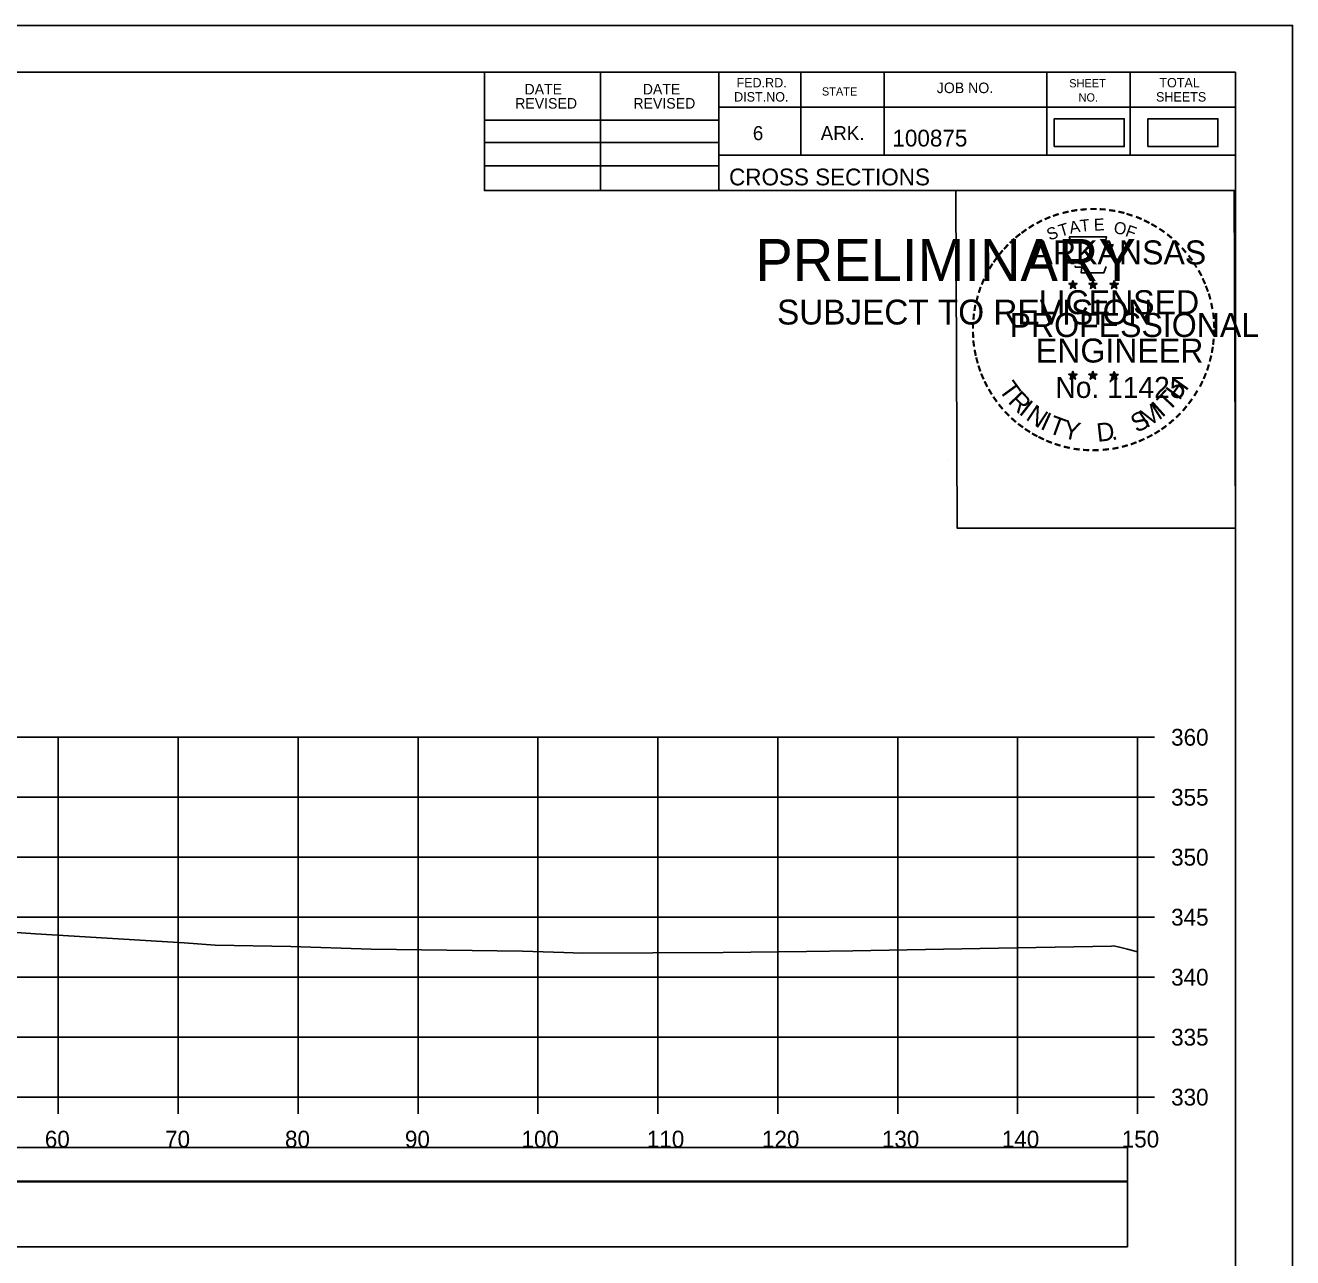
# Model space of a CAD drawing. Extents: x 1368122 to 1710785, y 373130 to 557566.
# Drawn here: x 1368746.1 to 1368851.8, y 374734.3 to 374837 of the extents above; entities that cross this region are included whole.
import ezdxf

# ---------------------------------------------------------------- set-up
doc = ezdxf.new("R2010")
doc.units = 0
for name, color, linetype in [('R_Alt Surface', 7, 'Continuous'), ('R_Axis', 7, 'Continuous'), ('R_Axis Annot', 7, 'Continuous'), ('R_Border', 7, 'Continuous'), ('R_Border PE', 7, 'Continuous'), ('R_Border Prem', 7, 'Continuous'), ('R_Drive', 7, 'Continuous'), ('R_Exist Surface', 7, 'Continuous'), ('R_Grid', 7, 'Continuous'), ('R_No Plot', 7, 'Continuous')]:
    doc.layers.add(name, color=color, linetype=linetype)

msp = doc.modelspace()

# ---------------------------------------------------------------- linework, layer by layer
at = {"layer": 'R_Alt Surface'}
for points in [[(1368539.73, 374740.67), (1368838.03, 374740.67), (1368838.03, 374743.48), (1368539.73, 374743.48)], [(1368539.73, 374735.2), (1368838.03, 374735.2), (1368838.03, 374740.61), (1368539.73, 374740.61)]]:
    msp.add_lwpolyline(points, close=True, dxfattribs=at)
at = {"layer": 'R_Axis'}
for p, q in [((1368838.88, 374747.68), (1368838.88, 374777.68)), ((1368840.28, 374777.68), (1368838.88, 374777.68)), ((1368840.28, 374772.68), (1368838.88, 374772.68)), ((1368840.28, 374767.68), (1368838.88, 374767.68)), ((1368840.28, 374762.68), (1368838.88, 374762.68)), ((1368840.28, 374757.68), (1368838.88, 374757.68)), ((1368840.28, 374752.68), (1368838.88, 374752.68)), ((1368538.88, 374747.68), (1368838.88, 374747.68)), ((1368748.88, 374746.28), (1368748.88, 374747.68)), ((1368758.88, 374746.28), (1368758.88, 374747.68)), ((1368768.88, 374746.28), (1368768.88, 374747.68)), ((1368778.88, 374746.28), (1368778.88, 374747.68)), ((1368788.88, 374746.28), (1368788.88, 374747.68)), ((1368798.88, 374746.28), (1368798.88, 374747.68)), ((1368808.88, 374746.28), (1368808.88, 374747.68)), ((1368818.88, 374746.28), (1368818.88, 374747.68)), ((1368828.88, 374746.28), (1368828.88, 374747.68)), ((1368838.88, 374746.28), (1368838.88, 374747.68)), ((1368840.28, 374747.68), (1368838.88, 374747.68))]:
    msp.add_line(p, q, dxfattribs=at)
at = {"layer": 'R_Border'}
for p, q in [((1368530.88, 374833.14), (1368847.06, 374833.14)), ((1368784.42, 374823.26), (1368784.42, 374833.14)), ((1368794.1, 374823.26), (1368794.1, 374833.14)), ((1368803.96, 374833.14), (1368803.96, 374823.26)), ((1368810.8, 374833.14), (1368810.8, 374826.2)), ((1368817.74, 374833.14), (1368817.74, 374826.2)), ((1368831.32, 374833.14), (1368831.32, 374826.2)), ((1368838.26, 374833.14), (1368838.26, 374826.2)), ((1368847.06, 374627.68), (1368847.06, 374833.14)), ((1368847.06, 374830.2), (1368803.96, 374830.2)), ((1368847.06, 374830.22), (1368847.06, 374830.22)), ((1368784.42, 374829.12), (1368803.96, 374829.12)), ((1368784.42, 374827.26), (1368803.96, 374827.26)), ((1368847.06, 374826.2), (1368803.96, 374826.2)), ((1368806.92, 374826.2), (1368847.06, 374826.2)), ((1368784.42, 374825.32), (1368803.96, 374825.32)), ((1368847.06, 374823.26), (1368784.42, 374823.26))]:
    msp.add_line(p, q, dxfattribs=at)
at = {"layer": 'R_Border PE'}
for p, q in [((1368833.49, 374815.76), (1368833.45, 374815.51)), ((1368833.49, 374815.4), (1368833.49, 374815.76)), ((1368833.49, 374815.76), (1368833.54, 374815.51)), ((1368835.16, 374815.76), (1368835.12, 374815.51)), ((1368835.16, 374815.4), (1368835.16, 374815.76)), ((1368835.16, 374815.76), (1368835.21, 374815.51)), ((1368836.93, 374815.75), (1368836.89, 374815.5)), ((1368836.93, 374815.39), (1368836.93, 374815.75)), ((1368836.93, 374815.75), (1368836.98, 374815.5)), ((1368833.15, 374815.51), (1368833.49, 374815.4)), ((1368833.15, 374815.51), (1368833.4, 374815.47)), ((1368833.15, 374815.51), (1368833.38, 374815.39)), ((1368833.28, 374815.1), (1368833.49, 374815.4)), ((1368833.28, 374815.1), (1368833.4, 374815.35)), ((1368833.28, 374815.1), (1368833.49, 374815.32)), ((1368833.84, 374815.51), (1368833.49, 374815.4)), ((1368833.71, 374815.1), (1368833.49, 374815.4)), ((1368833.71, 374815.1), (1368833.49, 374815.32)), ((1368833.84, 374815.51), (1368833.56, 374815.46)), ((1368833.71, 374815.1), (1368833.57, 374815.39)), ((1368833.84, 374815.51), (1368833.64, 374815.41)), ((1368834.82, 374815.51), (1368835.16, 374815.4)), ((1368834.82, 374815.51), (1368835.07, 374815.47)), ((1368834.82, 374815.51), (1368835.05, 374815.39)), ((1368834.95, 374815.1), (1368835.16, 374815.4)), ((1368834.95, 374815.1), (1368835.07, 374815.35)), ((1368834.95, 374815.1), (1368835.16, 374815.32)), ((1368835.51, 374815.51), (1368835.16, 374815.4)), ((1368835.38, 374815.1), (1368835.16, 374815.4)), ((1368835.38, 374815.1), (1368835.16, 374815.32)), ((1368835.51, 374815.51), (1368835.23, 374815.46)), ((1368835.38, 374815.1), (1368835.24, 374815.39)), ((1368835.51, 374815.51), (1368835.31, 374815.41)), ((1368836.58, 374815.5), (1368836.93, 374815.39)), ((1368836.58, 374815.5), (1368836.83, 374815.45)), ((1368836.58, 374815.5), (1368836.82, 374815.38)), ((1368836.71, 374815.09), (1368836.93, 374815.39)), ((1368836.71, 374815.09), (1368836.84, 374815.33)), ((1368836.71, 374815.09), (1368836.93, 374815.31)), ((1368837.28, 374815.5), (1368836.93, 374815.39)), ((1368837.14, 374815.09), (1368836.93, 374815.39)), ((1368837.14, 374815.09), (1368836.93, 374815.3)), ((1368837.28, 374815.5), (1368836.99, 374815.45)), ((1368837.14, 374815.09), (1368837, 374815.38)), ((1368837.28, 374815.5), (1368837.07, 374815.4)), ((1368833.49, 374808.19), (1368833.45, 374807.94)), ((1368833.49, 374807.83), (1368833.49, 374808.19)), ((1368833.49, 374808.19), (1368833.54, 374807.94)), ((1368835.16, 374808.19), (1368835.12, 374807.94)), ((1368835.16, 374807.83), (1368835.16, 374808.19)), ((1368835.16, 374808.19), (1368835.21, 374807.94)), ((1368836.93, 374808.18), (1368836.89, 374807.93)), ((1368836.93, 374807.82), (1368836.93, 374808.18)), ((1368836.93, 374808.18), (1368836.98, 374807.93)), ((1368833.14, 374807.94), (1368833.49, 374807.83)), ((1368833.14, 374807.94), (1368833.39, 374807.89)), ((1368833.14, 374807.94), (1368833.38, 374807.82)), ((1368833.27, 374807.53), (1368833.49, 374807.83)), ((1368833.27, 374807.53), (1368833.4, 374807.77)), ((1368833.27, 374807.53), (1368833.49, 374807.75)), ((1368833.84, 374807.94), (1368833.49, 374807.83)), ((1368833.7, 374807.53), (1368833.49, 374807.83)), ((1368833.7, 374807.53), (1368833.49, 374807.74)), ((1368833.84, 374807.94), (1368833.55, 374807.89)), ((1368833.7, 374807.53), (1368833.57, 374807.82)), ((1368833.84, 374807.94), (1368833.63, 374807.84)), ((1368834.81, 374807.94), (1368835.16, 374807.83)), ((1368834.81, 374807.94), (1368835.06, 374807.89)), ((1368834.81, 374807.94), (1368835.05, 374807.82)), ((1368834.94, 374807.53), (1368835.16, 374807.83)), ((1368834.94, 374807.53), (1368835.07, 374807.77)), ((1368834.94, 374807.53), (1368835.16, 374807.75)), ((1368835.51, 374807.94), (1368835.16, 374807.83)), ((1368835.37, 374807.53), (1368835.16, 374807.83)), ((1368835.37, 374807.53), (1368835.16, 374807.74)), ((1368835.51, 374807.94), (1368835.22, 374807.89)), ((1368835.37, 374807.53), (1368835.24, 374807.82)), ((1368835.51, 374807.94), (1368835.3, 374807.84)), ((1368836.58, 374807.93), (1368836.93, 374807.82)), ((1368836.58, 374807.93), (1368836.83, 374807.88)), ((1368836.58, 374807.93), (1368836.81, 374807.81)), ((1368836.71, 374807.52), (1368836.93, 374807.82)), ((1368836.71, 374807.52), (1368836.84, 374807.76)), ((1368836.71, 374807.52), (1368836.92, 374807.74)), ((1368837.14, 374807.52), (1368836.92, 374807.73)), ((1368837.27, 374807.93), (1368836.93, 374807.82)), ((1368837.14, 374807.52), (1368836.93, 374807.82)), ((1368837.27, 374807.93), (1368836.99, 374807.88)), ((1368837.14, 374807.52), (1368837, 374807.81)), ((1368837.27, 374807.93), (1368837.07, 374807.83))]:
    msp.add_line(p, q, dxfattribs=at)
for points in [[(1368833.19, 374819.39), (1368833.46, 374818.56)], [(1368836.7, 374818.47), (1368836.84, 374818.75), (1368836.15, 374818.73), (1368836.3, 374819.39), (1368833.19, 374819.39)], [(1368833.68, 374816.97), (1368833.68, 374816.88), (1368834.24, 374816.86), (1368834.19, 374816.39), (1368836.06, 374816.39), (1368836.26, 374816.92)], [(1368833.49, 374815.76), (1368833.71, 374815.1), (1368833.15, 374815.51), (1368833.84, 374815.51), (1368833.28, 374815.1), (1368833.49, 374815.76)], [(1368835.16, 374815.76), (1368835.38, 374815.1), (1368834.82, 374815.51), (1368835.51, 374815.51), (1368834.95, 374815.1), (1368835.16, 374815.76)], [(1368836.93, 374815.75), (1368837.14, 374815.09), (1368836.58, 374815.5), (1368837.28, 374815.5), (1368836.71, 374815.09), (1368836.93, 374815.75)], [(1368833.49, 374808.19), (1368833.7, 374807.53), (1368833.14, 374807.94), (1368833.84, 374807.94), (1368833.27, 374807.53), (1368833.49, 374808.19)], [(1368835.16, 374808.19), (1368835.37, 374807.53), (1368834.81, 374807.94), (1368835.51, 374807.94), (1368834.94, 374807.53), (1368835.16, 374808.19)], [(1368836.93, 374808.18), (1368837.14, 374807.52), (1368836.58, 374807.93), (1368837.27, 374807.93), (1368836.71, 374807.52), (1368836.93, 374808.18)]]:
    msp.add_lwpolyline(points, dxfattribs=at)
for centre, radius in [((1368833.49, 374815.4), 0.172), ((1368833.49, 374815.4), 0.145), ((1368835.16, 374815.4), 0.172), ((1368835.16, 374815.4), 0.145), ((1368836.93, 374815.39), 0.172), ((1368836.93, 374815.39), 0.145), ((1368833.49, 374815.4), 0.116), ((1368833.49, 374815.4), 0.0991), ((1368833.49, 374815.4), 0.0747), ((1368833.49, 374815.4), 0.0495), ((1368833.49, 374815.4), 0.0296), ((1368835.16, 374815.4), 0.116), ((1368835.16, 374815.4), 0.0991), ((1368835.16, 374815.4), 0.0747), ((1368835.16, 374815.4), 0.0495), ((1368835.16, 374815.4), 0.0296), ((1368836.93, 374815.39), 0.116), ((1368836.93, 374815.39), 0.0991), ((1368836.93, 374815.39), 0.0747), ((1368836.93, 374815.39), 0.0495), ((1368836.93, 374815.39), 0.0296), ((1368833.49, 374807.83), 0.172), ((1368833.49, 374807.83), 0.145), ((1368833.49, 374807.83), 0.116), ((1368833.49, 374807.83), 0.0991), ((1368833.49, 374807.83), 0.0747), ((1368833.49, 374807.83), 0.0495), ((1368833.49, 374807.83), 0.0296), ((1368835.16, 374807.83), 0.172), ((1368835.16, 374807.83), 0.145), ((1368835.16, 374807.83), 0.116), ((1368835.16, 374807.83), 0.0991), ((1368835.16, 374807.83), 0.0747), ((1368835.16, 374807.83), 0.0495), ((1368835.16, 374807.83), 0.0296), ((1368836.93, 374807.82), 0.172), ((1368836.93, 374807.82), 0.145), ((1368836.93, 374807.82), 0.116), ((1368836.93, 374807.82), 0.0991), ((1368836.93, 374807.82), 0.0747), ((1368836.93, 374807.82), 0.0495), ((1368836.93, 374807.82), 0.0296)]:
    msp.add_circle(centre, radius, dxfattribs=at)
at = {"layer": 'R_Drive'}
for points in [[(1368831.93, 374826.93), (1368837.77, 374826.93), (1368837.77, 374829.24), (1368831.93, 374829.24)], [(1368839.74, 374826.93), (1368845.58, 374826.93), (1368845.58, 374829.24), (1368839.74, 374829.24)]]:
    msp.add_lwpolyline(points, close=True, dxfattribs=at)
at = {"layer": 'R_Exist Surface'}
msp.add_lwpolyline([(1368739.79, 374761.78), (1368746.98, 374761.28), (1368759.37, 374760.53), (1368761.96, 374760.35), (1368768.28, 374760.25), (1368774.97, 374760.02), (1368787.6, 374759.84), (1368791.04, 374759.74), (1368792.6, 374759.67), (1368804.33, 374759.75), (1368811.27, 374759.83), (1368815.14, 374759.88), (1368825.73, 374760.06), (1368836.7, 374760.27), (1368836.85, 374760.29), (1368837.26, 374760.2), (1368838.05, 374760.02), (1368838.88, 374759.8)], dxfattribs=at)
at = {"layer": 'R_Grid'}
for p, q in [((1368538.88, 374777.68), (1368838.88, 374777.68)), ((1368748.88, 374747.68), (1368748.88, 374777.68)), ((1368758.88, 374747.68), (1368758.88, 374777.68)), ((1368768.88, 374747.68), (1368768.88, 374777.68)), ((1368778.88, 374747.68), (1368778.88, 374777.68)), ((1368788.88, 374747.68), (1368788.88, 374777.68)), ((1368798.88, 374747.68), (1368798.88, 374777.68)), ((1368808.88, 374747.68), (1368808.88, 374777.68)), ((1368818.88, 374747.68), (1368818.88, 374777.68)), ((1368828.88, 374747.68), (1368828.88, 374777.68)), ((1368838.88, 374747.68), (1368838.88, 374777.68)), ((1368538.88, 374772.68), (1368838.88, 374772.68)), ((1368538.88, 374767.68), (1368838.88, 374767.68)), ((1368538.88, 374762.68), (1368838.88, 374762.68)), ((1368538.88, 374757.68), (1368838.88, 374757.68)), ((1368538.88, 374752.68), (1368838.88, 374752.68)), ((1368538.88, 374747.68), (1368838.88, 374747.68))]:
    msp.add_line(p, q, dxfattribs=at)
at = {"layer": 'R_No Plot'}
for p, q in [((1368518.48, 374837.03), (1368851.81, 374837.03)), ((1368823.09, 374800.8), (1368823.09, 374800.8))]:
    msp.add_line(p, q, dxfattribs=at)
for points in [[(1368518.47, 374837.03), (1368851.81, 374837.03), (1368851.81, 374623.69), (1368518.47, 374623.69)], [(1368764.8, 374833.14), (1368784.42, 374833.14), (1368784.42, 374823.26), (1368800.53, 374823.26), (1368823.73, 374823.26), (1368823.85, 374795.1), (1368847.06, 374795.1), (1368847.06, 374627.68), (1368530.88, 374627.68), (1368530.88, 374833.14)], [(1368823.73, 374823.26), (1368846.94, 374823.26), (1368847.06, 374795.1), (1368823.85, 374795.1)]]:
    msp.add_lwpolyline(points, close=True, dxfattribs=at)

# ---------------------------------------------------------------- texts
at = {"layer": 'R_Axis Annot'}
for s, p in [('360', (1368841.68, 374776.98)), ('355', (1368841.68, 374771.98)), ('350', (1368841.68, 374766.98)), ('345', (1368841.68, 374761.98)), ('340', (1368841.68, 374756.98)), ('335', (1368841.68, 374751.98)), ('330', (1368841.68, 374746.98)), ('60', (1368747.76, 374743.48)), ('70', (1368757.79, 374743.48)), ('80', (1368767.79, 374743.48)), ('90', (1368777.79, 374743.48)), ('100', (1368787.51, 374743.48)), ('110', (1368797.96, 374743.48)), ('120', (1368807.56, 374743.48)), ('130', (1368817.56, 374743.48)), ('140', (1368827.56, 374743.48)), ('150', (1368837.56, 374743.48))]:
    msp.add_text(s, height=1.4, dxfattribs=at).set_placement(p)
at = {"layer": 'R_Border'}
for s, height, p in [('FED.RD.', 0.782, (1368805.44, 374831.86)), ('SHEET', 0.684, (1368833.18, 374831.86)), ('TOTAL', 0.782, (1368840.7, 374831.86)), ('DATE', 0.879, (1368787.76, 374831.27)), ('DATE', 0.879, (1368797.62, 374831.27)), ('DIST.NO.', 0.782, (1368805.24, 374830.68)), ('STATE', 0.684, (1368812.56, 374831.18)), ('JOB NO.', 0.879, (1368822.14, 374831.38)), ('SHEETS', 0.782, (1368840.42, 374830.68)), ('REVISED', 0.879, (1368786.98, 374830.09)), ('REVISED', 0.879, (1368796.84, 374830.09)), ('NO.', 0.684, (1368833.96, 374830.68)), ('6', 1.17, (1368806.8, 374827.46)), ('ARK.', 1.172, (1368812.46, 374827.46)), ('100875', 1.4, (1368818.44, 374826.93)), ('CROSS SECTIONS', 1.4, (1368804.82, 374823.69))]:
    msp.add_text(s, height=height, rotation=360, dxfattribs=at).set_placement(p)
at = {"layer": 'R_Border PE'}
for s, height, rotation, p in [('-', 1.6, 28.7918, (1368830.67, 374819.93)), ('-', 1.6, 24.3072, (1368831.3, 374820.25)), ('-', 1.6, 19.1761, (1368831.93, 374820.52)), ('-', 1.6, 13.6301, (1368832.68, 374820.76)), ('-', 1.6, 10.2193, (1368833.36, 374820.92)), ('T', 1, 6.0228, (1368834.13, 374819.81)), ('-', 1.6, 5.8968, (1368834.09, 374821.03)), ('-', 1.6, 0.1862, (1368834.86, 374821.1)), ('E', 1, 0.8323, (1368835.24, 374819.92)), ('-', 1.6, 357.743, (1368835.59, 374821.09)), ('-', 1.6, 352.1617, (1368836.33, 374821.03)), ('-', 1.6, 347.2049, (1368837.05, 374820.92)), ('-', 1.6, 342.3362, (1368837.68, 374820.76)), ('-', 1.6, 337.8551, (1368838.42, 374820.54)), ('-', 1.6, 334.1211, (1368839.05, 374820.27)), ('-', 1.6, 36.2317, (1368829.49, 374819.16)), ('-', 1.6, 34.0636, (1368830.07, 374819.56)), ('S', 1, 21.594, (1368831.54, 374819.07)), ('T', 1, 16.4036, (1368832.46, 374819.4)), ('A', 1, 11.2132, (1368833.28, 374819.65)), ('O', 1, 350.4515, (1368836.84, 374819.71)), ('F', 1, 340.0707, (1368837.79, 374819.49)), ('-', 1.6, 329.6409, (1368839.63, 374819.99)), ('-', 1.6, 325.8627, (1368840.27, 374819.62)), ('-', 1.6, 48.423, (1368828.14, 374817.89)), ('-', 1.6, 42.9622, (1368828.58, 374818.37)), ('-', 1.6, 38.9507, (1368829.02, 374818.79)), ('ARKANSAS', 2, 360, (1368830.04, 374817.1)), ('-', 1.6, 320.5297, (1368840.88, 374819.2)), ('-', 1.6, 315.5786, (1368841.48, 374818.71)), ('-', 1.6, 54.2325, (1368827.32, 374816.84)), ('-', 1.6, 50.6142, (1368827.73, 374817.41)), ('-', 1.6, 309.8797, (1368842.05, 374818.16)), ('-', 1.6, 306.6522, (1368842.58, 374817.56)), ('-', 1.6, 58.0706, (1368826.99, 374816.31)), ('-', 1.4, 303.6753, (1368843.06, 374816.99)), ('-', 1.6, 299.6684, (1368843.38, 374816.38)), ('-', 1.6, 67.7743, (1368826.42, 374815.09)), ('-', 1.6, 62.8713, (1368826.68, 374815.7)), ('-', 1.6, 294.6628, (1368843.7, 374815.77)), ('-', 1.6, 75.461, (1368826.01, 374813.74)), ('-', 1.6, 72.3945, (1368826.2, 374814.46)), ('LICENSED', 2, 360, (1368830.64, 374812.95)), ('DWB', 0.01, 360, (1368833.48, 374815.39)), ('DWB', 0.01, 360, (1368835.15, 374815.39)), ('DWB', 0.01, 360, (1368836.92, 374815.38)), ('-', 1.6, 290.5728, (1368843.96, 374815.19)), ('-', 1.6, 285.1233, (1368844.2, 374814.61)), ('-', 1.6, 81.2013, (1368825.87, 374813.03)), ('-', 1.6, 280.5493, (1368844.4, 374813.87)), ('-', 1.6, 85.1863, (1368825.8, 374812.34)), ('PROFESSIONAL', 2, 360, (1368828.21, 374811.05)), ('-', 1.6, 276.5962, (1368844.56, 374813.1)), ('-', 1.6, 94.1959, (1368825.81, 374810.91)), ('-', 1.6, 89.0622, (1368825.77, 374811.64)), ('-', 1.6, 274.3301, (1368844.62, 374812.38)), ('-', 1.6, 269.9407, (1368844.65, 374811.75)), ('-', 1.6, 98.9479, (1368825.88, 374810.25)), ('ENGINEER', 2, 360, (1368830.4, 374808.92)), ('-', 1.6, 260.9953, (1368844.56, 374810.43)), ('-', 1.6, 263.5172, (1368844.63, 374811.08)), ('-', 1.6, 101.7149, (1368826.02, 374809.51)), ('-', 1.6, 105.4578, (1368826.18, 374808.92)), ('-', 1.6, 255.7626, (1368844.45, 374809.75)), ('-', 1.6, 109.0874, (1368826.39, 374808.29)), ('-', 1.6, 252.8681, (1368844.27, 374809.03)), ('-', 1.6, 114.0643, (1368826.65, 374807.69)), ('-', 1.6, 115.7289, (1368826.95, 374807.07)), ('T', 1.54, 306.0406, (1368827.25, 374806.66)), ('No. 11425', 1.757, 360, (1368832.03, 374805.97)), ('DWB', 0.01, 360, (1368833.48, 374807.82)), ('DWB', 0.01, 360, (1368835.15, 374807.82)), ('DWB', 0.01, 360, (1368836.91, 374807.81)), ('H', 1.54, 54.6088, (1368842.37, 374805.7)), ('-', 1.6, 244.6197, (1368843.79, 374807.73)), ('-', 1.6, 247.8887, (1368844.05, 374808.36)), ('-', 1.6, 120.4471, (1368827.31, 374806.49)), ('-', 1.6, 125.8934, (1368827.71, 374805.93)), ('R', 1.54, 314.005, (1368828.01, 374805.62)), ('T', 1.54, 46.6444, (1368841.48, 374804.76)), ('-', 1.6, 239.0712, (1368843.39, 374806.98)), ('-', 1.6, 130.7181, (1368828.17, 374805.37)), ('I', 1.54, 321.9694, (1368828.91, 374804.68)), ('N', 1.54, 326.5002, (1368829.48, 374804.21)), ('M', 1.54, 32.6563, (1368839.63, 374803.43)), ('I', 1.54, 42.1136, (1368840.92, 374804.28)), ('-', 1.6, 231.2538, (1368842.56, 374805.76)), ('-', 1.6, 233.8452, (1368842.99, 374806.33)), ('-', 1.6, 134.2238, (1368828.69, 374804.83)), ('-', 1.6, 138.9338, (1368829.22, 374804.36)), ('I', 1.54, 335.3603, (1368830.69, 374803.43)), ('T', 1.54, 339.8912, (1368831.35, 374803.1)), ('Y', 1.54, 347.8556, (1368832.57, 374802.65)), ('D', 1.54, 6.3969, (1368835.55, 374802.3)), ('S', 1.54, 26.9312, (1368838.8, 374803.03)), ('-', 1.6, 221.0851, (1368841.56, 374804.69)), ('-', 1.6, 225.7653, (1368842.08, 374805.2)), ('-', 1.6, 144.6463, (1368829.77, 374803.96)), ('-', 1.6, 148.0898, (1368830.33, 374803.59)), ('-', 1.6, 151.5704, (1368830.91, 374803.26)), ('-', 1.6, 207.3568, (1368839.92, 374803.48)), ('-', 1.6, 212.2491, (1368840.48, 374803.83)), ('-', 1.6, 215.7363, (1368841.01, 374804.21)), ('-', 1.6, 154.6002, (1368831.43, 374803.02)), ('-', 1.6, 158.5612, (1368832.06, 374802.76)), ('-', 1.6, 162.7983, (1368832.74, 374802.55)), ('-', 1.6, 167.5555, (1368833.46, 374802.38)), ('-', 1.6, 173.1155, (1368834.23, 374802.27)), ('-', 1.6, 185.8167, (1368836.53, 374802.32)), ('-', 1.6, 191.2858, (1368837.27, 374802.45)), ('.', 1.54, 13.7642, (1368836.74, 374802.42)), ('-', 1.6, 195.4743, (1368838, 374802.65)), ('-', 1.6, 200.7184, (1368838.67, 374802.89)), ('-', 1.6, 204.2516, (1368839.29, 374803.16)), ('-', 1.6, 176.5183, (1368834.98, 374802.22)), ('-', 1.6, 181.5918, (1368835.72, 374802.24))]:
    msp.add_text(s, height=height, rotation=rotation, dxfattribs=at).set_placement(p)
at = {"layer": 'R_Border Prem'}
for s, height, p in [('PRELIMINARY', 3.5, (1368807.01, 374815.72)), ('DWB', 0.01, (1368807.76, 374817.57)), ('SUBJECT TO REVISION', 2.0751, (1368808.82, 374812.09))]:
    msp.add_text(s, height=height, rotation=360, dxfattribs=at).set_placement(p)

doc.saveas('drawing.dxf')
